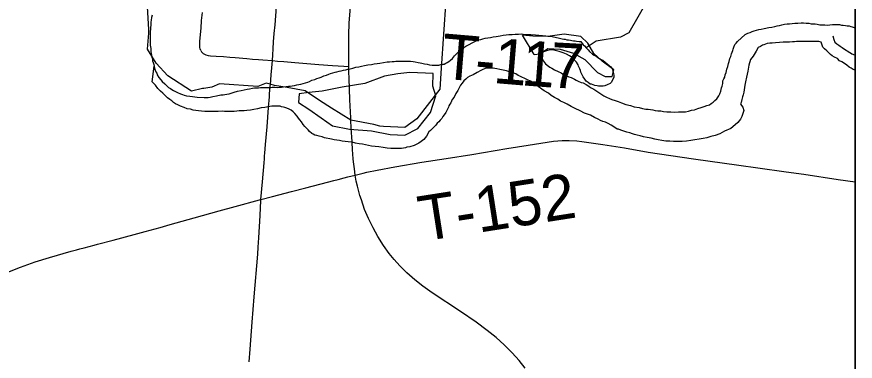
# Model space of a CAD drawing. Extents: x -1.4 to 35.4, y 0 to 22.
# Drawn here: x 22.805 to 23.86, y 16.239 to 16.672 of the extents above; entities that cross this region are included whole.
import ezdxf

# ---------------------------------------------------------------- set-up
doc = ezdxf.new("R2010")
doc.units = 0
for name, color, linetype in [('GM_X_City_Street', 7, 'Continuous'), ('GM_X_Corporation', 7, 'Continuous'), ('GM_X_County_Road', 7, 'Continuous'), ('GM_X_Major_River', 7, 'Continuous'), ('GM_X_Minor_River', 7, 'Continuous'), ('GM_X_State_Route', 7, 'Continuous'), ('GM_X_Township_Road', 7, 'Continuous'), ('GM_X_Township_Road_Text', 7, 'Continuous'), ('SC_Scratch1', 7, 'Continuous'), ('SH_Border', 7, 'Continuous')]:
    doc.layers.add(name, color=color, linetype=linetype)

msp = doc.modelspace()

# ---------------------------------------------------------------- linework, layer by layer
at = {"layer": 'GM_X_City_Street'}
for points in [[(23.0368, 16.6295), (23.0362, 16.6312), (23.0357, 16.6331), (23.0355, 16.6348), (23.0355, 16.6374), (23.0357, 16.6408), (23.0364, 16.6495), (23.0371, 16.6573), (23.0379, 16.6669), (23.0389, 16.6772)], [(23.0368, 16.6295), (23.0378, 16.6278), (23.0387, 16.6266), (23.0399, 16.6254), (23.0413, 16.6245), (23.043, 16.6239), (23.0461, 16.6232), (23.0492, 16.6227), (23.0561, 16.6222), (23.0654, 16.6216), (23.0734, 16.6211), (23.08, 16.6206), (23.0949, 16.6192), (23.102, 16.6186), (23.1092, 16.6178), (23.115, 16.6174), (23.1268, 16.6167), (23.1334, 16.6161), (23.1412, 16.6154), (23.1549, 16.6144), (23.1851, 16.6119), (23.2025, 16.6106), (23.2168, 16.6096), (23.2229, 16.6091)]]:
    msp.add_lwpolyline(points, dxfattribs=at)
at = {"layer": 'GM_X_Corporation'}
msp.add_lwpolyline([(23.345, 16.6924), (23.3391, 16.6071), (23.3373, 16.5808), (23.3083, 16.5435), (23.2935, 16.5325), (23.2664, 16.534), (23.2621, 16.5343), (23.2544, 16.5363), (23.2254, 16.5416), (23.201, 16.5568), (23.1863, 16.5666), (23.168, 16.5787), (23.1453, 16.5827), (23.1297, 16.5853), (23.1241, 16.5868), (23.1191, 16.5881), (23.1085, 16.5842), (23.0603, 16.5873), (23.0508, 16.5831), (23.0408, 16.5817), (23.0388, 16.5814), (23.0252, 16.5781), (22.9953, 16.5973), (22.9806, 16.6132), (22.9697, 16.6308), (22.9716, 16.6511), (22.9714, 16.6557), (22.9694, 16.6913)], dxfattribs=at)
at = {"layer": 'GM_X_County_Road'}
for points in [[(23.1268, 16.6167), (23.1273, 16.6237), (23.1278, 16.6316), (23.1284, 16.6401), (23.1292, 16.6505), (23.1303, 16.6617), (23.1322, 16.6842)], [(23.1242, 16.5853), (23.1243, 16.5863), (23.1254, 16.5989), (23.1261, 16.6076), (23.1268, 16.6167)], [(23.1124, 16.442), (23.1143, 16.4645), (23.1164, 16.488), (23.1168, 16.4934), (23.1171, 16.4969), (23.1174, 16.5003), (23.1179, 16.5057), (23.1183, 16.5111), (23.1202, 16.5333), (23.1221, 16.5575), (23.1232, 16.5712), (23.1234, 16.5745), (23.1242, 16.5853)], [(23.1124, 16.442), (23.1268, 16.4458), (23.1508, 16.452), (23.1691, 16.4567), (23.1962, 16.464), (23.204, 16.4659), (23.2094, 16.4672), (23.2172, 16.4693), (23.2218, 16.4705), (23.2311, 16.4728)], [(22.7881, 16.3484), (22.81, 16.3572), (22.8287, 16.3638), (22.8464, 16.3694), (22.8739, 16.3771), (22.8805, 16.3789), (22.8846, 16.38), (22.89, 16.3814), (22.8966, 16.3831), (22.9026, 16.3847), (22.9068, 16.3858), (22.9266, 16.3911), (22.953, 16.398), (22.9668, 16.4018), (22.9859, 16.407), (22.9985, 16.4105), (23.0284, 16.419), (23.06, 16.4277), (23.0801, 16.4334), (23.1105, 16.4415), (23.1124, 16.442)], [(23.0977, 16.238), (23.0991, 16.2541), (23.1015, 16.2881), (23.1041, 16.3197), (23.1084, 16.3735), (23.1091, 16.3822), (23.1099, 16.394), (23.1115, 16.4219), (23.1123, 16.4408), (23.1124, 16.442)]]:
    msp.add_lwpolyline(points, dxfattribs=at)
at = {"layer": 'GM_X_Major_River'}
for points in [[(22.9755, 16.6739), (22.975, 16.6708), (22.9746, 16.6674), (22.9742, 16.6648), (22.9742, 16.6621), (22.9733, 16.6522), (22.9733, 16.6496), (22.9732, 16.6469), (22.9732, 16.6443), (22.9732, 16.642), (22.9731, 16.6393), (22.9731, 16.6359), (22.9734, 16.634), (22.9738, 16.6317), (22.9741, 16.6279), (22.9745, 16.6256), (22.9748, 16.6233), (22.9752, 16.6207), (22.9759, 16.6188), (22.9763, 16.6165), (22.977, 16.6142), (22.9777, 16.6119), (22.9781, 16.6096), (22.9788, 16.6069), (22.9795, 16.6046), (22.9803, 16.6027), (22.9814, 16.6008), (22.9821, 16.5989), (22.984, 16.5955), (22.9866, 16.5924), (22.9881, 16.5905), (22.9915, 16.5874), (22.9945, 16.5843), (22.9963, 16.5827), (22.9986, 16.5816), (23.0005, 16.5804), (23.0024, 16.5792), (23.0058, 16.5773), (23.0076, 16.5765), (23.0114, 16.5749), (23.0137, 16.5741), (23.016, 16.5733)], [(23.6995, 16.6094), (23.7003, 16.6128), (23.7014, 16.6155), (23.7022, 16.6193), (23.7034, 16.6219), (23.7042, 16.625), (23.705, 16.6272), (23.7058, 16.6291), (23.7062, 16.631), (23.707, 16.6333), (23.7085, 16.6367), (23.7101, 16.6386), (23.7116, 16.6408), (23.7212, 16.6494), (23.7247, 16.6509), (23.7277, 16.652), (23.73, 16.6531), (23.7327, 16.6542), (23.7357, 16.6549), (23.7384, 16.6556), (23.7414, 16.656), (23.7452, 16.657), (23.7513, 16.6581), (23.7551, 16.6588), (23.7586, 16.6595), (23.7616, 16.6602), (23.7646, 16.6609), (23.7673, 16.6617), (23.7707, 16.6624), (23.7742, 16.6627), (23.7772, 16.663), (23.7806, 16.6634), (23.784, 16.6637), (23.7878, 16.6637), (23.792, 16.664), (23.7947, 16.6639), (23.7981, 16.6635), (23.8015, 16.6635), (23.8042, 16.663), (23.8068, 16.6626), (23.8095, 16.6626), (23.8121, 16.6622), (23.8152, 16.6617), (23.817, 16.6617), (23.8197, 16.6617), (23.8216, 16.6616), (23.8243, 16.6612), (23.8311, 16.6619), (23.8341, 16.6618), (23.8368, 16.6618), (23.8402, 16.6618), (23.8425, 16.6613), (23.8448, 16.6613), (23.8474, 16.6609), (23.8497, 16.6605), (23.8523, 16.6601), (23.8542, 16.6596), (23.8561, 16.6589), (23.8584, 16.6584), (23.8598, 16.6581)], [(23.3278, 16.611), (23.33, 16.611), (23.3331, 16.6109), (23.3361, 16.6109), (23.3388, 16.6116), (23.3411, 16.612), (23.343, 16.6123), (23.3449, 16.6134), (23.3468, 16.6142), (23.3487, 16.6153), (23.351, 16.6171), (23.3533, 16.6194), (23.356, 16.6224), (23.3587, 16.6254), (23.3618, 16.6284), (23.3648, 16.6306), (23.3675, 16.6329), (23.3702, 16.6347), (23.3725, 16.6358), (23.3798, 16.6399), (23.3821, 16.641), (23.3843, 16.6418), (23.3866, 16.6425), (23.3889, 16.6432), (23.3916, 16.6439), (23.3946, 16.6446), (23.3977, 16.6454), (23.4011, 16.6457), (23.4045, 16.6464), (23.4083, 16.6471), (23.4133, 16.6478), (23.4171, 16.6485), (23.4209, 16.6488), (23.4243, 16.6492), (23.4285, 16.6495), (23.4323, 16.6498), (23.4365, 16.6497), (23.4403, 16.6501), (23.4441, 16.6496), (23.4479, 16.6496), (23.452, 16.6495), (23.4577, 16.6491), (23.4619, 16.6486), (23.4664, 16.6482), (23.4706, 16.6477), (23.4736, 16.6473), (23.4767, 16.6473), (23.4786, 16.6469), (23.4805, 16.6464), (23.4824, 16.646), (23.4843, 16.6456), (23.4861, 16.6452), (23.4911, 16.644), (23.4933, 16.6436), (23.4952, 16.6436), (23.4971, 16.6428), (23.4994, 16.6428), (23.5017, 16.6423), (23.5036, 16.6419), (23.5055, 16.6415), (23.5074, 16.6415), (23.5093, 16.6411), (23.5127, 16.6407), (23.5149, 16.6406), (23.5175, 16.6364), (23.5194, 16.6352), (23.5213, 16.6325), (23.5239, 16.6302), (23.5258, 16.6279), (23.5292, 16.6248), (23.5314, 16.6233), (23.5341, 16.6221), (23.536, 16.6206), (23.5382, 16.6194), (23.5401, 16.6178), (23.5424, 16.617), (23.5457, 16.6143), (23.5476, 16.6128), (23.5503, 16.6105), (23.5525, 16.6089), (23.5544, 16.6058), (23.5551, 16.6028), (23.5558, 16.6005), (23.5562, 16.5978), (23.5561, 16.5959), (23.5534, 16.5895), (23.5515, 16.588), (23.548, 16.5862), (23.545, 16.5851), (23.5427, 16.5847), (23.5404, 16.5844), (23.537, 16.5844), (23.5351, 16.5848), (23.5325, 16.5853), (23.5302, 16.586), (23.5283, 16.5868), (23.5264, 16.5872), (23.5238, 16.5892), (23.5215, 16.5907), (23.5197, 16.5934), (23.5178, 16.5961)], [(23.4562, 16.6242), (23.463, 16.6253), (23.4734, 16.6319), (23.4889, 16.6308), (23.5055, 16.6259), (23.5198, 16.618), (23.5358, 16.6018), (23.5452, 16.5966), (23.554, 16.5968), (23.5564, 16.6052), (23.5414, 16.6161), (23.531, 16.6254), (23.5236, 16.6385), (23.5147, 16.647), (23.4938, 16.6497), (23.4733, 16.6467), (23.4543, 16.6475), (23.4415, 16.6484)], [(23.4562, 16.6242), (23.4415, 16.6484)], [(23.7693, 16.6396), (23.7644, 16.6393), (23.7594, 16.639), (23.7553, 16.6387), (23.7526, 16.6387), (23.7492, 16.638), (23.7469, 16.6373), (23.745, 16.6365), (23.7431, 16.6358), (23.7408, 16.6343), (23.7377, 16.6332), (23.7354, 16.6283), (23.7315, 16.6223), (23.728, 16.6181), (23.726, 16.611), (23.7248, 16.6034), (23.7232, 16.5958), (23.722, 16.5901), (23.7208, 16.5856), (23.7204, 16.5829), (23.72, 16.5799), (23.7195, 16.5768), (23.7187, 16.5734), (23.718, 16.5712), (23.7172, 16.5678), (23.7163, 16.564), (23.7156, 16.5621), (23.7167, 16.5602), (23.7185, 16.5582), (23.7196, 16.554), (23.7185, 16.5502), (23.7173, 16.5465), (23.7153, 16.5431), (23.7138, 16.5408), (23.7122, 16.5389), (23.7088, 16.5359), (23.7034, 16.5311), (23.6954, 16.5278), (23.6897, 16.5248), (23.6836, 16.5226), (23.6782, 16.5212), (23.6733, 16.5197), (23.6687, 16.5187), (23.6531, 16.5162), (23.6474, 16.5152), (23.6421, 16.5149), (23.636, 16.515), (23.6314, 16.515), (23.6265, 16.5155), (23.6216, 16.5155), (23.6167, 16.5164), (23.6121, 16.5172), (23.6076, 16.518), (23.603, 16.5192), (23.5981, 16.5201), (23.5935, 16.5209), (23.5894, 16.5221), (23.5856, 16.5229), (23.5822, 16.5237), (23.5795, 16.5245), (23.5765, 16.5257), (23.5727, 16.5265), (23.569, 16.5281), (23.5652, 16.5293), (23.5622, 16.5305), (23.5603, 16.5305), (23.5561, 16.5336), (23.5527, 16.5355), (23.549, 16.5375), (23.5456, 16.5391), (23.5425, 16.5403), (23.5395, 16.5414), (23.5365, 16.543), (23.532, 16.545), (23.5267, 16.5481), (23.5195, 16.5505), (23.5138, 16.5536), (23.5078, 16.5563), (23.5025, 16.5591), (23.4976, 16.5618), (23.4935, 16.5638), (23.4893, 16.5657), (23.4856, 16.5681), (23.4818, 16.5704), (23.4776, 16.5727), (23.4739, 16.5755), (23.4686, 16.5786), (23.4581, 16.5863), (23.4547, 16.5887), (23.4513, 16.5906), (23.4475, 16.5926), (23.4441, 16.5941), (23.4407, 16.5957), (23.4381, 16.5969), (23.4358, 16.5981), (23.4328, 16.6), (23.4286, 16.6012), (23.4252, 16.6024), (23.4211, 16.6036), (23.4169, 16.6048), (23.4127, 16.6056)], [(23.8598, 16.6047), (23.8596, 16.6048), (23.857, 16.6056), (23.8547, 16.6072), (23.8521, 16.6084), (23.8494, 16.6107), (23.8461, 16.613), (23.843, 16.615), (23.84, 16.6165), (23.8374, 16.6192), (23.8336, 16.6208), (23.8306, 16.6227), (23.8287, 16.6243), (23.8268, 16.6258), (23.8239, 16.6289), (23.8212, 16.6316), (23.819, 16.6336), (23.8168, 16.6397), (23.8141, 16.6408), (23.8084, 16.6405), (23.8016, 16.6406), (23.7959, 16.6407), (23.7898, 16.6408), (23.786, 16.6405), (23.7834, 16.6401), (23.7807, 16.6402), (23.7773, 16.6399), (23.7739, 16.6399), (23.7693, 16.6396)], [(23.8317, 16.6478), (23.8328, 16.6432), (23.8342, 16.6398), (23.8365, 16.6375), (23.8391, 16.6359), (23.841, 16.6347), (23.8433, 16.6332), (23.8452, 16.632), (23.8528, 16.6268)], [(23.5178, 16.5961), (23.5163, 16.5988), (23.5148, 16.6022), (23.5141, 16.6041), (23.5134, 16.6064), (23.5119, 16.6095), (23.5112, 16.6114), (23.5093, 16.6145), (23.5078, 16.6164), (23.5048, 16.6191), (23.5025, 16.6214), (23.5003, 16.6226), (23.4965, 16.6249), (23.4946, 16.6257), (23.4927, 16.6265), (23.4901, 16.6273), (23.4874, 16.6281), (23.4806, 16.6297), (23.478, 16.6301), (23.4749, 16.6298), (23.473, 16.6291), (23.4704, 16.6283), (23.4677, 16.6276), (23.4658, 16.6269), (23.4646, 16.6235), (23.4661, 16.6193), (23.4679, 16.6158), (23.4705, 16.6124), (23.4739, 16.6097), (23.4758, 16.6085), (23.4784, 16.6069), (23.4818, 16.605), (23.4864, 16.603), (23.4898, 16.6011), (23.4935, 16.5987), (23.4969, 16.5976), (23.4996, 16.5964), (23.5026, 16.5952), (23.5049, 16.594), (23.5068, 16.5932), (23.509, 16.5921), (23.5113, 16.5909), (23.5151, 16.5893), (23.5177, 16.5885), (23.5215, 16.5866), (23.5234, 16.5854), (23.5252, 16.5842), (23.5279, 16.5823), (23.5309, 16.5807), (23.5335, 16.5792), (23.5437, 16.5722), (23.5471, 16.5706), (23.5509, 16.569), (23.5539, 16.5678), (23.5577, 16.5663), (23.5618, 16.5651), (23.566, 16.5635), (23.5713, 16.5615), (23.577, 16.5603), (23.5819, 16.5587), (23.5879, 16.5575), (23.5921, 16.5566), (23.5963, 16.5558), (23.5993, 16.5554), (23.6023, 16.555), (23.6054, 16.5546), (23.6084, 16.5541), (23.6114, 16.5537), (23.6152, 16.5533), (23.6186, 16.5528), (23.6228, 16.5524), (23.6281, 16.5523), (23.6327, 16.5519), (23.6376, 16.5522), (23.6422, 16.5521), (23.6463, 16.5524), (23.6501, 16.5531), (23.654, 16.5542), (23.6578, 16.5549), (23.662, 16.5564), (23.6662, 16.5578), (23.67, 16.5589), (23.673, 16.56), (23.6764, 16.5611), (23.6787, 16.5626), (23.681, 16.5645), (23.6833, 16.5663), (23.6857, 16.5686), (23.6884, 16.5723), (23.6895, 16.575), (23.6907, 16.5784), (23.6915, 16.5822), (23.6923, 16.5845), (23.6931, 16.5879), (23.6935, 16.5913), (23.6947, 16.5939), (23.6959, 16.5958), (23.6963, 16.5988), (23.6975, 16.6015), (23.6983, 16.6057), (23.6995, 16.6094)], [(23.8528, 16.6268), (23.8538, 16.6262), (23.8557, 16.625), (23.8587, 16.6239), (23.8598, 16.6235)], [(23.1217, 16.5585), (23.1175, 16.5578), (23.1129, 16.5571), (23.108, 16.556), (23.1034, 16.5553), (23.0992, 16.5543), (23.0947, 16.554), (23.0913, 16.5536), (23.0882, 16.5533), (23.0852, 16.5533), (23.0821, 16.553), (23.0787, 16.5527), (23.0753, 16.5527), (23.0723, 16.5528), (23.0696, 16.5528), (23.0666, 16.5528), (23.0639, 16.5529), (23.0586, 16.5526), (23.054, 16.5526), (23.0419, 16.5528), (23.0377, 16.5532), (23.0339, 16.5537), (23.0305, 16.5541), (23.0271, 16.5545), (23.0237, 16.5554), (23.0199, 16.5562), (23.0161, 16.5577), (23.0112, 16.5593), (23.0078, 16.5609), (23.0052, 16.5625), (23.0026, 16.564), (23.0003, 16.566), (22.9977, 16.5679), (22.995, 16.5698), (22.9924, 16.5725), (22.989, 16.5756), (22.986, 16.5783), (22.983, 16.5814), (22.9797, 16.5856), (22.9774, 16.5883), (22.9755, 16.5899), (22.9781, 16.6096)], [(23.016, 16.5733), (23.019, 16.5725), (23.0232, 16.5721), (23.0262, 16.5717), (23.0292, 16.5712), (23.0323, 16.5708), (23.041, 16.5703), (23.0433, 16.5703), (23.0459, 16.5702), (23.0486, 16.5706), (23.052, 16.5717), (23.0566, 16.5724), (23.0619, 16.5734), (23.0649, 16.5738), (23.0672, 16.5741), (23.0695, 16.5745), (23.0725, 16.5748), (23.0752, 16.5755), (23.079, 16.577), (23.0828, 16.5781), (23.0874, 16.5791), (23.0912, 16.5798), (23.095, 16.5806), (23.0981, 16.5813), (23.1019, 16.582), (23.1042, 16.5823), (23.1068, 16.5823), (23.1095, 16.5826), (23.1118, 16.583), (23.1137, 16.5829), (23.1216, 16.5828), (23.1247, 16.5828), (23.1266, 16.5831), (23.1285, 16.5831), (23.1304, 16.5831), (23.133, 16.583), (23.1357, 16.5834), (23.1383, 16.5833), (23.141, 16.5837), (23.144, 16.584), (23.1471, 16.5844), (23.1494, 16.5847), (23.1516, 16.5851), (23.1547, 16.5854), (23.1574, 16.5861), (23.16, 16.5865), (23.1627, 16.5872), (23.1657, 16.5879), (23.1684, 16.5886), (23.1715, 16.5897), (23.1737, 16.5904), (23.1764, 16.5919), (23.1802, 16.593), (23.1829, 16.5941), (23.1856, 16.5948), (23.1882, 16.5959), (23.1917, 16.5974), (23.1947, 16.5985), (23.1978, 16.5996), (23.2001, 16.6003), (23.2027, 16.6014), (23.2058, 16.6021), (23.2081, 16.6025), (23.2107, 16.6032), (23.2134, 16.6039), (23.2161, 16.6047), (23.2191, 16.605), (23.2218, 16.6057), (23.2248, 16.6064), (23.2282, 16.6071), (23.2317, 16.6082), (23.2355, 16.6089), (23.2389, 16.6096), (23.2427, 16.6104), (23.2469, 16.6111), (23.2515, 16.6117), (23.2549, 16.6125), (23.2587, 16.6128), (23.2621, 16.6135), (23.2712, 16.6149), (23.2743, 16.6152), (23.2773, 16.6156), (23.28, 16.6155), (23.2823, 16.6159), (23.2853, 16.6158), (23.2876, 16.6158), (23.2899, 16.6161), (23.2921, 16.6161), (23.294, 16.6161), (23.2959, 16.616), (23.2982, 16.616), (23.3005, 16.616), (23.3039, 16.6155), (23.3062, 16.6151), (23.3103, 16.6143), (23.3126, 16.6139), (23.3149, 16.6135), (23.3183, 16.6127), (23.3213, 16.6123), (23.3244, 16.6115), (23.3278, 16.611)], [(23.4127, 16.6056), (23.4093, 16.6064), (23.4067, 16.6068), (23.4044, 16.6073), (23.4021, 16.6073), (23.3987, 16.6073), (23.3953, 16.607), (23.3934, 16.6063), (23.3915, 16.6055), (23.3888, 16.6041), (23.3842, 16.6015), (23.3793, 16.5989), (23.375, 16.597), (23.3724, 16.5952), (23.3701, 16.5933), (23.3678, 16.5911), (23.3655, 16.5884), (23.3635, 16.5858), (23.362, 16.5832), (23.36, 16.579), (23.3577, 16.5752), (23.3554, 16.5707), (23.353, 16.5677), (23.3511, 16.5636), (23.3499, 16.5617), (23.3488, 16.5598), (23.3484, 16.5579), (23.3472, 16.5556), (23.3449, 16.5515), (23.3429, 16.5485), (23.3414, 16.5462), (23.3398, 16.544), (23.3379, 16.5417), (23.336, 16.5398), (23.3341, 16.538), (23.3325, 16.5357), (23.3302, 16.5334), (23.3279, 16.5308), (23.3256, 16.5286), (23.3237, 16.5271), (23.3206, 16.5218), (23.3171, 16.5173), (23.314, 16.5151), (23.311, 16.5128), (23.3052, 16.5099), (23.2995, 16.5084), (23.2961, 16.5077), (23.2942, 16.507), (23.2919, 16.5066), (23.2892, 16.5063), (23.2858, 16.506), (23.282, 16.506), (23.2759, 16.5061), (23.271, 16.5066), (23.2661, 16.5074), (23.2608, 16.5082), (23.2559, 16.5087), (23.2517, 16.5091), (23.2479, 16.5099), (23.2441, 16.5107), (23.2403, 16.5116), (23.2358, 16.512), (23.2312, 16.5128), (23.2271, 16.514), (23.2221, 16.5145), (23.2183, 16.5149), (23.2146, 16.5154), (23.2112, 16.5162), (23.2081, 16.5166), (23.2047, 16.517), (23.2013, 16.5178), (23.1922, 16.5195), (23.1896, 16.5207), (23.1858, 16.5215), (23.1828, 16.5223), (23.1801, 16.5231), (23.1782, 16.5242), (23.1763, 16.525), (23.1737, 16.5277), (23.1718, 16.5297), (23.1696, 16.5316), (23.1677, 16.5339), (23.1655, 16.5362), (23.1636, 16.5397), (23.1614, 16.542), (23.1595, 16.5443), (23.158, 16.5466), (23.155, 16.55), (23.1531, 16.5523), (23.1505, 16.5543), (23.1479, 16.5558), (23.1452, 16.557), (23.1426, 16.5578), (23.1407, 16.5582), (23.1384, 16.5586), (23.1365, 16.5594), (23.1342, 16.5595), (23.132, 16.5595), (23.1297, 16.5595), (23.1263, 16.5592), (23.1217, 16.5585)], [(23.329, 16.6006), (23.2998, 16.6016), (23.2846, 16.6), (23.2679, 16.5969), (23.243, 16.5879), (23.2145, 16.5832), (23.1894, 16.5783), (23.1726, 16.5764), (23.1604, 16.5747), (23.1599, 16.5641), (23.1726, 16.5555), (23.1884, 16.5449), (23.2026, 16.5348), (23.2238, 16.5306), (23.2514, 16.5285), (23.2749, 16.5238), (23.2934, 16.5231), (23.3099, 16.5311), (23.3255, 16.5513), (23.3323, 16.5724), (23.3287, 16.5843)], [(23.3287, 16.5843), (23.329, 16.6006)]]:
    msp.add_lwpolyline(points, dxfattribs=at)
at = {"layer": 'GM_X_Minor_River'}
msp.add_lwpolyline([(23.6179, 16.7381), (23.6186, 16.7277), (23.5751, 16.6515), (23.5647, 16.646), (23.5339, 16.6409), (23.5213, 16.6325)], dxfattribs=at)
at = {"layer": 'GM_X_State_Route'}
for points in [[(23.2256, 16.5411), (23.2253, 16.5449), (23.2243, 16.5675), (23.2233, 16.5947), (23.2231, 16.602), (23.2229, 16.6091), (23.2228, 16.6133), (23.2228, 16.6185), (23.2229, 16.6323), (23.2229, 16.6487), (23.2236, 16.6639), (23.2245, 16.6789), (23.2248, 16.6834), (23.2253, 16.6935), (23.226, 16.7014), (23.2278, 16.7219), (23.2293, 16.7405), (23.2311, 16.7644), (23.2326, 16.7824), (23.2334, 16.7921)], [(23.4446, 16.2301), (23.437, 16.2398), (23.4284, 16.2495), (23.4183, 16.2596), (23.4082, 16.2687), (23.3971, 16.2777), (23.3831, 16.2879), (23.3636, 16.3012), (23.3277, 16.3247), (23.3161, 16.333), (23.3058, 16.3412), (23.2961, 16.3499), (23.2872, 16.3587), (23.2801, 16.3666), (23.2738, 16.3743), (23.2665, 16.3845), (23.2594, 16.3955), (23.2534, 16.4064), (23.2477, 16.4182), (23.2429, 16.4297), (23.2388, 16.4415), (23.237, 16.447), (23.2338, 16.4588), (23.2324, 16.4653), (23.2311, 16.4728), (23.23, 16.4808), (23.2292, 16.4863), (23.2285, 16.4929), (23.228, 16.4995), (23.2276, 16.5044), (23.2271, 16.5143), (23.2266, 16.5211), (23.2264, 16.5254), (23.226, 16.5327), (23.2256, 16.5411)]]:
    msp.add_lwpolyline(points, dxfattribs=at)
at = {"layer": 'GM_X_Township_Road'}
msp.add_lwpolyline([(23.2311, 16.4728), (23.2409, 16.4753), (23.2457, 16.4765), (23.2585, 16.4791), (23.281, 16.4831), (23.3149, 16.4888), (23.3455, 16.4938), (23.3775, 16.4987), (23.4217, 16.506), (23.4484, 16.5103), (23.4805, 16.5152), (23.4912, 16.5162), (23.5, 16.5161), (23.5097, 16.5156), (23.516, 16.5149), (23.5249, 16.5137), (23.5425, 16.5111), (23.5697, 16.507), (23.5996, 16.5017), (23.6562, 16.4933), (23.7134, 16.4854), (23.7374, 16.4819), (23.773, 16.4768), (23.7952, 16.4738), (23.8382, 16.4674), (23.8598, 16.4643)], dxfattribs=at)
at = {"layer": 'SC_Scratch1'}
msp.add_lwpolyline([(23.8598, 15.0361), (23.8598, 16.7067)], dxfattribs=at)
at = {"layer": 'SH_Border'}
msp.add_lwpolyline([(17.0598, 19.8546), (23.8598, 19.8546), (23.8598, 13.0546), (17.0598, 13.0546)], close=True, dxfattribs=at)

# ---------------------------------------------------------------- texts
at = {"layer": 'GM_X_Township_Road_Text'}
for s, height, rotation, p in [('T', 0.0568, 355.1428, (23.3377, 16.5942)), ('1', 0.0568, 355.2767, (23.4035, 16.5886)), ('1', 0.0568, 355.685, (23.4388, 16.5857)), ('7', 0.0568, 356.9734, (23.4751, 16.583)), ('-', 0.0568, 355.1704, (23.3801, 16.5906)), ('T-152', 0.05682, 8.8708, (23.3153, 16.3893))]:
    msp.add_text(s, height=height, rotation=rotation, dxfattribs=at).set_placement(p)

doc.saveas('drawing.dxf')
